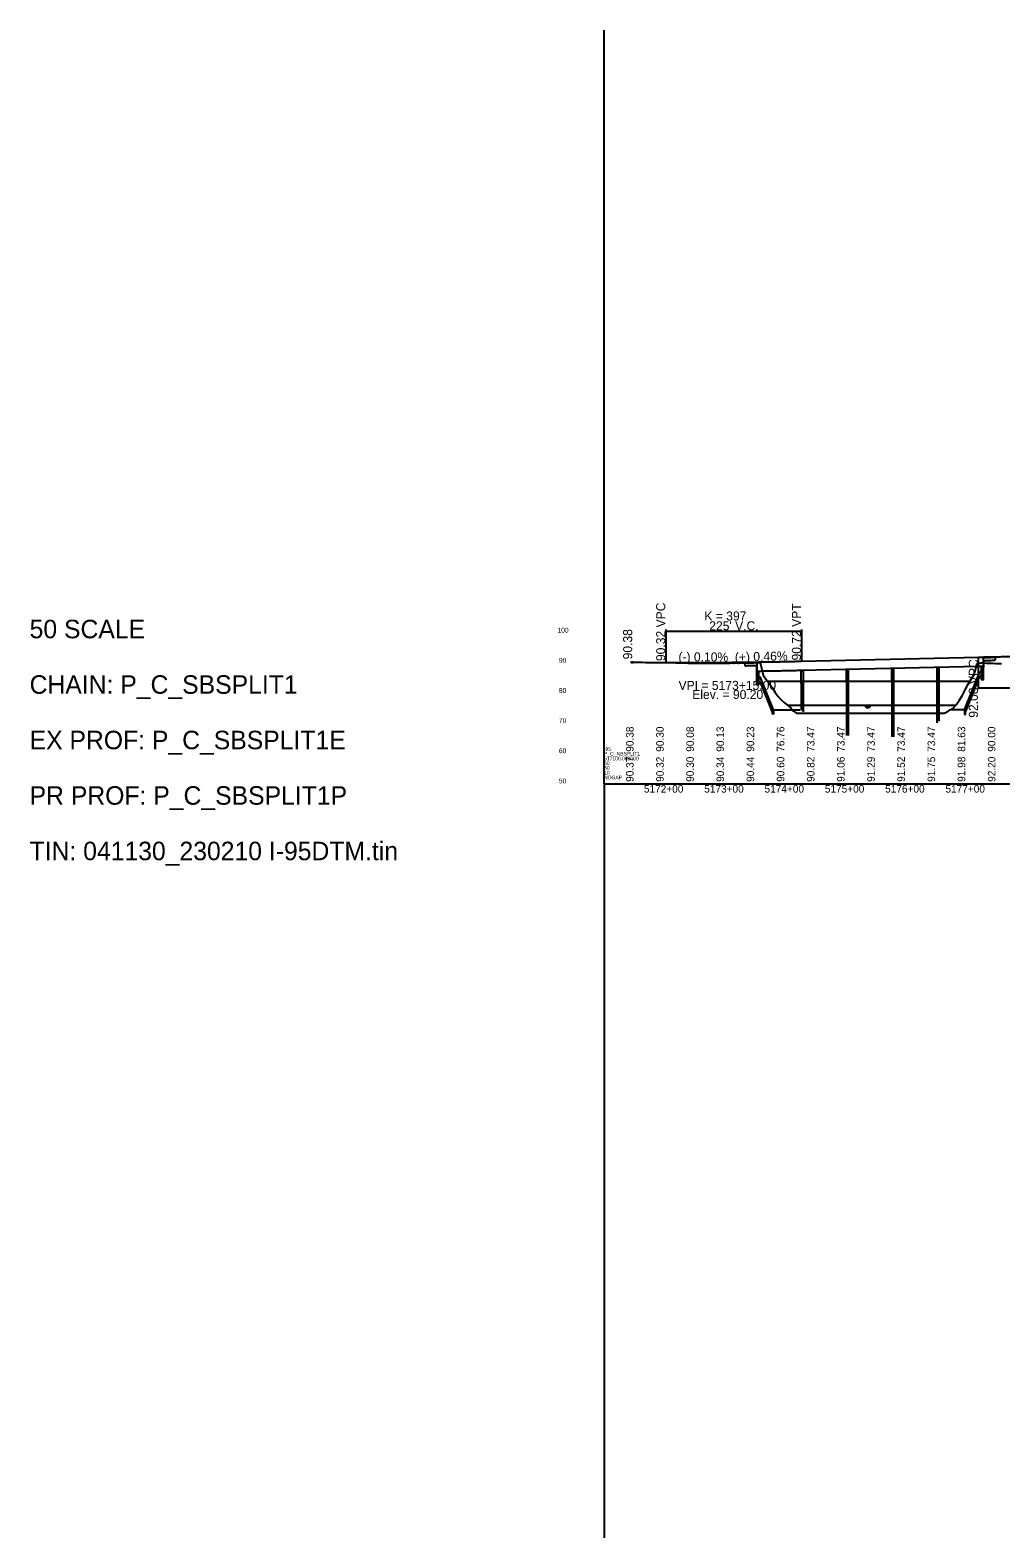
# Model space of a CAD drawing. Extents: x 2121671 to 2169879, y 557274 to 599957.
# Drawn here: x 2145717 to 2147326, y 591457 to 593957 of the extents above; entities that cross this region are included whole.
import ezdxf

# ---------------------------------------------------------------- set-up
doc = ezdxf.new("R2010")
doc.units = 0
for name, color, linetype in [('BR_CONCRETE', 7, 'Continuous'), ('BR_DETAILS', 7, 'Continuous'), ('BR_PRESTRESSED BEAM', 7, 'Continuous'), ('RD_DDB_ElevTX', 7, 'Continuous'), ('RD_DDB_GradeTX', 7, 'Continuous'), ('RD_DDB_Profile_Elev', 7, 'Continuous'), ('RD_DDB_Profile_EX', 7, 'Continuous'), ('RD_DDB_Profile_Lbl', 7, 'Continuous'), ('RD_DDB_Profile_PR', 7, 'Continuous'), ('RD_DDB_StaTX', 7, 'Continuous'), ('RD_DDB_StripGrade', 7, 'Continuous'), ('RD_DDB_VCLbl', 7, 'Continuous'), ('RD_GPK_Profile_Cell', 7, 'Continuous'), ('RD_HC_Data_Rel', 7, 'Continuous')]:
    doc.layers.add(name, color=color, linetype=linetype)

msp = doc.modelspace()

# ---------------------------------------------------------------- linework, layer by layer
at = {"layer": 'BR_CONCRETE'}
for p, q in [((2146901.8, 592908.6), (2146901.8, 592903.6)), ((2146901.8, 592908.6), (2146901.8, 592903.6)), ((2146921.1, 592903.9), (2146921.1, 592892.7)), ((2146921.1, 592903.9), (2146921.1, 592892.7)), ((2146921.8, 592909.7), (2146921.8, 592892.7)), ((2146921.8, 592909.7), (2146921.8, 592892.7)), ((2146995.7, 592911.1), (2147289.1, 592917.9)), ((2146995.7, 592911.1), (2147289.1, 592917.9)), ((2147289.1, 592917.9), (2147296.8, 592918)), ((2147289.1, 592917.9), (2147296.8, 592918)), ((2147296.8, 592918), (2147296.8, 592901)), ((2147296.8, 592918), (2147296.8, 592901)), ((2147297.5, 592912.2), (2147297.5, 592901)), ((2147297.5, 592912.2), (2147297.5, 592901)), ((2147316.8, 592917.6), (2147316.8, 592912.6)), ((2147316.8, 592917.6), (2147316.8, 592912.6)), ((2147070.3, 592875.8), (2147070.3, 592787.8)), ((2147070.3, 592875.8), (2147070.3, 592787.8)), ((2147073.3, 592875.8), (2147073.3, 592787.7)), ((2147073.3, 592875.8), (2147073.3, 592787.7)), ((2147145.3, 592877.6), (2147145.3, 592785.6)), ((2147145.3, 592877.6), (2147145.3, 592785.6)), ((2147148.3, 592877.6), (2147148.3, 592785.6)), ((2147148.3, 592877.6), (2147148.3, 592785.6)), ((2147220.3, 592879.3), (2147220.3, 592808.9)), ((2147220.3, 592879.3), (2147220.3, 592808.9)), ((2147223.3, 592879.3), (2147223.3, 592811.7)), ((2147223.3, 592879.3), (2147223.3, 592811.7)), ((2146995.3, 592874.1), (2146995.3, 592829.3)), ((2146995.3, 592874.1), (2146995.3, 592829.3)), ((2146998.3, 592874.1), (2146998.3, 592827.2)), ((2146998.3, 592874.1), (2146998.3, 592827.2))]:
    msp.add_line(p, q, dxfattribs=at)
for points in [[(2147293.5, 592881), (2147297.5, 592881), (2147297.5, 592901), (2147293.5, 592901)], [(2147293.5, 592881), (2147297.5, 592881), (2147297.5, 592901), (2147293.5, 592901)], [(2146921.1, 592872.7), (2146925.1, 592872.7), (2146925.1, 592892.7), (2146921.1, 592892.7)], [(2146921.1, 592872.7), (2146925.1, 592872.7), (2146925.1, 592892.7), (2146921.1, 592892.7)], [(2146994.8, 592874.1), (2146998.8, 592874.1), (2146998.8, 592894.1), (2146994.8, 592894.1)], [(2146994.8, 592874.1), (2146998.8, 592874.1), (2146998.8, 592894.1), (2146994.8, 592894.1)], [(2147069.8, 592875.8), (2147073.8, 592875.8), (2147073.8, 592895.8), (2147069.8, 592895.8)], [(2147069.8, 592875.8), (2147073.8, 592875.8), (2147073.8, 592895.8), (2147069.8, 592895.8)], [(2147144.8, 592877.6), (2147148.8, 592877.6), (2147148.8, 592897.6), (2147144.8, 592897.6)], [(2147144.8, 592877.6), (2147148.8, 592877.6), (2147148.8, 592897.6), (2147144.8, 592897.6)], [(2147219.8, 592879.3), (2147223.8, 592879.3), (2147223.8, 592899.3), (2147219.8, 592899.3)], [(2147219.8, 592879.3), (2147223.8, 592879.3), (2147223.8, 592899.3), (2147219.8, 592899.3)]]:
    msp.add_lwpolyline(points, close=True, dxfattribs=at)
for points in [[(2146901.8, 592908.6), (2146905.6, 592908.7), (2146910.1, 592908.7), (2146914.6, 592908.8), (2146919.1, 592908.8), (2146921.8, 592908.9)], [(2146901.8, 592908.6), (2146905.6, 592908.7), (2146910.1, 592908.7), (2146914.6, 592908.8), (2146919.1, 592908.8), (2146921.8, 592908.9)], [(2146901.8, 592903.6), (2146905.6, 592903.7), (2146910.1, 592903.7), (2146914.6, 592903.8), (2146919.1, 592903.8), (2146921.8, 592903.9)], [(2146901.8, 592903.6), (2146905.6, 592903.7), (2146910.1, 592903.7), (2146914.6, 592903.8), (2146919.1, 592903.8), (2146921.8, 592903.9)], [(2146921.8, 592909.7), (2146923.7, 592909.7), (2146928.2, 592909.8), (2146932.7, 592909.9), (2146937.2, 592909.9), (2146941.7, 592910), (2146946.2, 592910.1), (2146950.7, 592910.2), (2146955.2, 592910.2), (2146959.7, 592910.3), (2146964.2, 592910.4), (2146968.7, 592910.5), (2146973.2, 592910.6), (2146977.7, 592910.7), (2146982.2, 592910.8), (2146986.7, 592910.9), (2146991.2, 592911), (2146995.7, 592911.1)], [(2146921.8, 592909.7), (2146923.7, 592909.7), (2146928.2, 592909.8), (2146932.7, 592909.9), (2146937.2, 592909.9), (2146941.7, 592910), (2146946.2, 592910.1), (2146950.7, 592910.2), (2146955.2, 592910.2), (2146959.7, 592910.3), (2146964.2, 592910.4), (2146968.7, 592910.5), (2146973.2, 592910.6), (2146977.7, 592910.7), (2146982.2, 592910.8), (2146986.7, 592910.9), (2146991.2, 592911), (2146995.7, 592911.1)], [(2147296.8, 592917.2), (2147298.1, 592917.2), (2147307.1, 592917.4), (2147316.1, 592917.6), (2147316.8, 592917.6)], [(2147296.8, 592917.2), (2147298.1, 592917.2), (2147307.1, 592917.4), (2147316.1, 592917.6), (2147316.8, 592917.6)], [(2147296.8, 592912.2), (2147298.1, 592912.2), (2147307.1, 592912.4), (2147316.1, 592912.6), (2147316.8, 592912.6)], [(2147296.8, 592912.2), (2147298.1, 592912.2), (2147307.1, 592912.4), (2147316.1, 592912.6), (2147316.8, 592912.6)]]:
    msp.add_spline(points, degree=3, dxfattribs=at)
at = {"layer": 'BR_DETAILS'}
for p, q in [((2146925.1, 592885.2), (2146927.1, 592885.2)), ((2146925.1, 592885.2), (2146927.1, 592885.2)), ((2146925.1, 592877.7), (2146927.1, 592877.7)), ((2146925.1, 592877.7), (2146927.1, 592877.7)), ((2146949, 592830.5), (2146927.1, 592885.2)), ((2146949, 592830.5), (2146927.1, 592885.2)), ((2146947.5, 592826.7), (2146927.1, 592877.7)), ((2146947.5, 592826.7), (2146927.1, 592877.7)), ((2147266.2, 592830.4), (2147291.5, 592893.5)), ((2147266.2, 592830.4), (2147291.5, 592893.5)), ((2147267.7, 592826.7), (2147291.5, 592886)), ((2147267.7, 592826.7), (2147291.5, 592886)), ((2147293.5, 592893.5), (2147291.5, 592893.5)), ((2147293.5, 592893.5), (2147291.5, 592893.5)), ((2147293.5, 592886), (2147291.5, 592886)), ((2147293.5, 592886), (2147291.5, 592886)), ((2146947.5, 592823), (2146947.5, 592826.7)), ((2146947.5, 592823), (2146947.5, 592826.7)), ((2146949, 592830.5), (2146993, 592830.5)), ((2146949, 592830.5), (2146949, 592823)), ((2146949, 592830.5), (2146993, 592830.5)), ((2146949, 592830.5), (2146949, 592823)), ((2147266.2, 592830.4), (2147244.7, 592830.4)), ((2147266.2, 592830.4), (2147244.7, 592830.4)), ((2147266.2, 592830.4), (2147266.2, 592822.9)), ((2147266.2, 592830.4), (2147266.2, 592822.9)), ((2147267.7, 592822.9), (2147267.7, 592826.7)), ((2147267.7, 592822.9), (2147267.7, 592826.7)), ((2146949, 592823), (2146947.5, 592823)), ((2146949, 592823), (2146947.5, 592823)), ((2147266.2, 592822.9), (2147267.7, 592822.9)), ((2147266.2, 592822.9), (2147267.7, 592822.9))]:
    msp.add_line(p, q, dxfattribs=at)
at = {"layer": 'BR_PRESTRESSED BEAM'}
for p, q in [((2146995.7, 592896.1), (2147289.1, 592902.9)), ((2146995.7, 592896.1), (2147289.1, 592902.9)), ((2147289.1, 592902.9), (2147296.8, 592903)), ((2147289.1, 592902.9), (2147296.8, 592903))]:
    msp.add_line(p, q, dxfattribs=at)
msp.add_spline([(2146921.8, 592894.7), (2146923.7, 592894.7), (2146928.2, 592894.8), (2146932.7, 592894.9), (2146937.2, 592894.9), (2146941.7, 592895), (2146946.2, 592895.1), (2146950.7, 592895.2), (2146955.2, 592895.2), (2146959.7, 592895.3), (2146964.2, 592895.4), (2146968.7, 592895.5), (2146973.2, 592895.6), (2146977.7, 592895.7), (2146982.2, 592895.8), (2146986.7, 592895.9), (2146991.2, 592896), (2146995.7, 592896.1)], degree=3, dxfattribs=at)
msp.add_spline([(2146921.8, 592894.7), (2146923.7, 592894.7), (2146928.2, 592894.8), (2146932.7, 592894.9), (2146937.2, 592894.9), (2146941.7, 592895), (2146946.2, 592895.1), (2146950.7, 592895.2), (2146955.2, 592895.2), (2146959.7, 592895.3), (2146964.2, 592895.4), (2146968.7, 592895.5), (2146973.2, 592895.6), (2146977.7, 592895.7), (2146982.2, 592895.8), (2146986.7, 592895.9), (2146991.2, 592896), (2146995.7, 592896.1)], degree=3, dxfattribs=at)
at = {"layer": 'RD_DDB_GradeTX'}
for p, q in [((2146821.2, 592908.8), (2146882.2, 592908.5)), ((2146945.2, 592909.9), (2146884.2, 592908.5))]:
    msp.add_line(p, q, dxfattribs=at)
for centre in [(2146715.2, 592909.3), (2146883.2, 592908.5)]:
    msp.add_circle(centre, 1, dxfattribs=at)
at = {"layer": 'RD_DDB_Profile_Elev'}
for p, q in [((2146939.2, 592878.1), (2147275.3, 592878.1)), ((2146972.4, 592838.1), (2147251.5, 592838.1)), ((2147100.5, 592836.8), (2147110.5, 592836.8)), ((2147101.7, 592835.6), (2147109.2, 592835.6)), ((2147103, 592834.3), (2147108, 592834.3))]:
    msp.add_line(p, q, dxfattribs=at)
at = {"layer": 'RD_DDB_Profile_EX'}
for points in [[(2146712.2, 592909.4), (2146717.2, 592909.4), (2146722.2, 592909.3), (2146727.2, 592909.3), (2146732.2, 592909.3), (2146737.2, 592909.2), (2146742.2, 592909.2), (2146747.2, 592909.2), (2146752.2, 592909.1), (2146757.2, 592909.1), (2146762.2, 592909), (2146767.2, 592909), (2146772.2, 592908.9), (2146777.2, 592908.8), (2146782.2, 592908.7), (2146787.2, 592908.6), (2146792.2, 592908.4), (2146797.2, 592908.3), (2146802.2, 592908.2), (2146807.2, 592908.1), (2146812.2, 592908), (2146817.2, 592907.9), (2146822.2, 592907.8), (2146827.2, 592907.7), (2146832.2, 592907.8), (2146837.2, 592907.8), (2146842.2, 592907.9), (2146847.2, 592907.9), (2146852.2, 592908), (2146857.2, 592908), (2146862.2, 592908.1), (2146867.2, 592908.1), (2146872.2, 592908.1), (2146877.2, 592908.1), (2146882.2, 592908.2), (2146887.2, 592908.2), (2146892.2, 592908.2), (2146897.2, 592908.3), (2146902.2, 592908.4), (2146907.2, 592908.4), (2146912.2, 592908.5), (2146917.2, 592908.6), (2146922.2, 592908.7), (2146927.2, 592908.8), (2146932.2, 592887.9), (2146937.2, 592880.5), (2146942.2, 592874.5), (2146947.2, 592867.6), (2146952.2, 592859), (2146957.2, 592852.7), (2146962.2, 592847), (2146967.2, 592842), (2146972.2, 592838.2), (2146977.2, 592834.1), (2146982.2, 592828), (2146987.2, 592824.8), (2146992.2, 592824.8), (2146997.2, 592824.8), (2147002.2, 592824.8), (2147007.2, 592824.8), (2147012.2, 592824.8), (2147017.2, 592824.8), (2147022.2, 592824.8), (2147027.2, 592824.8), (2147032.2, 592824.8), (2147037.2, 592824.8), (2147042.2, 592824.8), (2147047.2, 592824.8), (2147052.2, 592824.8), (2147057.2, 592824.8), (2147062.2, 592824.8), (2147067.2, 592824.8), (2147072.2, 592824.8), (2147077.2, 592824.8), (2147082.2, 592824.8), (2147087.2, 592824.8), (2147092.2, 592824.8), (2147097.2, 592824.8), (2147102.2, 592824.8), (2147107.2, 592824.8), (2147112.2, 592824.8), (2147117.2, 592824.8), (2147122.2, 592824.8), (2147127.2, 592824.8), (2147132.2, 592824.8), (2147137.2, 592824.8), (2147142.2, 592824.8), (2147147.2, 592824.8), (2147152.2, 592824.8), (2147157.2, 592824.8), (2147162.2, 592824.8), (2147167.2, 592824.8), (2147172.2, 592824.8), (2147177.2, 592824.8), (2147182.2, 592824.8), (2147187.2, 592824.8), (2147192.2, 592824.8), (2147197.2, 592824.8), (2147202.2, 592824.8), (2147207.2, 592824.8), (2147212.2, 592824.8)], [(2147212.2, 592824.8), (2147217.2, 592824.8), (2147222.2, 592824.8), (2147227.2, 592824.8), (2147232.2, 592824.8), (2147237.2, 592827.4), (2147242.2, 592830.3), (2147247.2, 592833.3), (2147252.2, 592838.8), (2147257.2, 592845.8), (2147262.2, 592853.9), (2147267.2, 592863.8), (2147272.2, 592873.2), (2147277.2, 592881.3), (2147282.2, 592889.1), (2147287.2, 592906.8), (2147292.2, 592908.3), (2147297.2, 592908.2), (2147302.2, 592908), (2147307.2, 592907.8), (2147312.2, 592907.7), (2147317.2, 592907.5), (2147322.2, 592907.3), (2147327.2, 592907.2)]]:
    msp.add_lwpolyline(points, dxfattribs=at)
at = {"layer": 'RD_DDB_Profile_PR'}
for p, q in [((2146715.2, 592909.3), (2146770.7, 592909.1)), ((2146995.7, 592911.1), (2147289.1, 592917.9))]:
    msp.add_line(p, q, dxfattribs=at)
for points in [[(2146770.7, 592909.1), (2146775.2, 592909), (2146779.7, 592909), (2146784.2, 592909), (2146788.7, 592909), (2146793.2, 592909), (2146797.7, 592909), (2146802.2, 592909), (2146806.7, 592909), (2146811.2, 592908.9), (2146815.7, 592908.9), (2146820.2, 592909), (2146824.7, 592909), (2146829.2, 592909), (2146833.7, 592909), (2146838.2, 592909), (2146842.7, 592909), (2146847.2, 592909), (2146851.7, 592909), (2146856.2, 592909.1), (2146860.7, 592909.1), (2146865.2, 592909.1), (2146869.7, 592909.2), (2146874.2, 592909.2), (2146878.7, 592909.2), (2146883.2, 592909.3), (2146887.7, 592909.3), (2146892.2, 592909.4), (2146896.7, 592909.4), (2146901.2, 592909.4), (2146905.7, 592909.5), (2146910.2, 592909.6), (2146914.7, 592909.6), (2146919.2, 592909.7), (2146923.7, 592909.7), (2146928.2, 592909.8), (2146932.7, 592909.9), (2146937.2, 592909.9), (2146941.7, 592910), (2146946.2, 592910.1), (2146950.7, 592910.2), (2146955.2, 592910.2), (2146959.7, 592910.3), (2146964.2, 592910.4), (2146968.7, 592910.5), (2146973.2, 592910.6), (2146977.7, 592910.7), (2146982.2, 592910.8), (2146986.7, 592910.9), (2146991.2, 592911), (2146995.7, 592911.1)], [(2147289.1, 592917.9), (2147298.1, 592918.1), (2147307.1, 592918.3), (2147316.1, 592918.4), (2147325.1, 592918.6), (2147334.1, 592918.8), (2147343.1, 592918.9), (2147352.1, 592919.1), (2147361.1, 592919.2), (2147370.1, 592919.4), (2147379.1, 592919.5), (2147388.1, 592919.6), (2147397.1, 592919.7), (2147406.1, 592919.8), (2147415.1, 592919.9), (2147424.1, 592920), (2147433.1, 592920), (2147442.1, 592920.1), (2147451.1, 592920.2), (2147460.1, 592920.2), (2147469.1, 592920.2), (2147478.1, 592920.3), (2147487.1, 592920.3), (2147496.1, 592920.3), (2147505.1, 592920.3), (2147514.1, 592920.3), (2147523.1, 592920.2), (2147532.1, 592920.2), (2147541.1, 592920.2), (2147550.1, 592920.1), (2147559.1, 592920.1), (2147568.1, 592920), (2147577.1, 592919.9), (2147586.1, 592919.8), (2147595.1, 592919.7), (2147604.1, 592919.6), (2147613.1, 592919.5), (2147622.1, 592919.4), (2147631.1, 592919.3), (2147640.1, 592919.1), (2147649.1, 592919), (2147658.1, 592918.8), (2147667.1, 592918.7), (2147676.1, 592918.5), (2147685.1, 592918.3), (2147694.1, 592918.1), (2147703.1, 592917.9), (2147712.1, 592917.7), (2147721.1, 592917.5), (2147730.1, 592917.3), (2147739.1, 592917)]]:
    msp.add_spline(points, degree=3, dxfattribs=at)
at = {"layer": 'RD_DDB_VCLbl'}
for p, q in [((2146770.7, 592963.6), (2146770.7, 592909.1)), ((2146770.7, 592961.1), (2146995.7, 592961.1)), ((2146995.7, 592963.6), (2146995.7, 592911.1)), ((2147289.1, 592864.5), (2147289.1, 592917.9)), ((2147289.1, 592867), (2147739.1, 592867))]:
    msp.add_line(p, q, dxfattribs=at)
at = {"layer": 'RD_GPK_Profile_Cell'}
for q in [(2146668.2, 593957.5), (2146668.2, 593957.5), (2151268.2, 592707.5), (2146668.2, 591457.5), (2151268.2, 592707.5), (2146668.2, 591457.5)]:
    msp.add_line((2146668.2, 592707.5), q, dxfattribs=at)

# ---------------------------------------------------------------- texts
at = {"layer": 'RD_DDB_ElevTX'}
for s, p in [('100', (2146591, 592958.5)), ('90', (2146593.4, 592908.5)), ('80', (2146593.4, 592858.5)), ('70', (2146593.4, 592808.5)), ('60', (2146593.4, 592758.5)), ('50', (2146593.4, 592708.5))]:
    msp.add_text(s, height=8, dxfattribs=at).set_placement(p)
at = {"layer": 'RD_DDB_GradeTX'}
for s, rotation, p in [('(-) 0.10%', 359.7004, (2146791.6, 592910.9)), ('(+) 0.46%', 1.3258, (2146885.3, 592910.5))]:
    msp.add_text(s, height=15, rotation=rotation, dxfattribs=at).set_placement(p)
at = {"layer": 'RD_DDB_Profile_Lbl'}
msp.add_text('90.38', height=15, rotation=90, dxfattribs=at).set_placement((2146714.9, 592914.1))
for s, p in [('VPI = 5173+15.00', (2146791.8, 592863.5)), ('Elev. = 90.20', (2146814.5, 592848.5))]:
    msp.add_text(s, height=15, dxfattribs=at).set_placement(p)
at = {"layer": 'RD_DDB_StaTX'}
for s, p in [('5172+00', (2146734.3, 592693.2)), ('5173+00', (2146834.3, 592693.2)), ('5174+00', (2146934.3, 592693.2)), ('5175+00', (2147034.3, 592693.2)), ('5176+00', (2147134.3, 592693.2)), ('5177+00', (2147234.3, 592693.2))]:
    msp.add_text(s, height=12.5, dxfattribs=at).set_placement(p)
at = {"layer": 'RD_DDB_StripGrade'}
for s, height, p in [('90.32 VPC', 15, (2146769.7, 592911.3)), ('90.72 VPT', 15, (2146994.7, 592912.3)), ('92.08 VPC', 15, (2147288.1, 592817.3)), ('90.38', 12.5, (2146717.2, 592760.9)), ('90.30', 12.5, (2146767.2, 592760.9)), ('90.08', 12.5, (2146817.2, 592760.9)), ('90.13', 12.5, (2146867.2, 592760.9)), ('90.23', 12.5, (2146917.2, 592760.9)), ('76.76', 12.5, (2146967.2, 592760.9)), ('73.47', 12.5, (2147017.2, 592760.9)), ('73.47', 12.5, (2147067.2, 592760.9)), ('73.47', 12.5, (2147117.2, 592760.9)), ('73.47', 12.5, (2147167.2, 592760.9)), ('73.47', 12.5, (2147217.2, 592760.9)), ('81.63', 12.5, (2147267.2, 592760.9)), ('90.00', 12.5, (2147317.2, 592760.9)), ('90.37', 12.5, (2146717.2, 592711)), ('90.32', 12.5, (2146767.2, 592711)), ('90.30', 12.5, (2146817.2, 592711)), ('90.34', 12.5, (2146867.2, 592711)), ('90.44', 12.5, (2146917.2, 592711)), ('90.60', 12.5, (2146967.2, 592711)), ('90.82', 12.5, (2147017.2, 592711)), ('91.06', 12.5, (2147067.2, 592711)), ('91.29', 12.5, (2147117.2, 592711)), ('91.52', 12.5, (2147167.2, 592711)), ('91.75', 12.5, (2147217.2, 592711)), ('91.98', 12.5, (2147267.2, 592711)), ('92.20', 12.5, (2147317.2, 592711))]:
    msp.add_text(s, height=height, rotation=90, dxfattribs=at).set_placement(p)
at = {"layer": 'RD_DDB_VCLbl'}
for s, p in [('K = 397', (2146834.6, 592978.6)), ("225' V.C.", (2146842.7, 592962.3))]:
    msp.add_text(s, height=15, dxfattribs=at).set_placement(p)
at = {"layer": 'RD_GPK_Profile_Cell'}
for s, height, p in [('517100.000000', 6, (2146668.2, 592746.8)), ('P_C_NBSPLIT1', 6, (2146668.2, 592754.7)), ('I95', 6, (2146668.2, 592762.5)), ('50', 6, (2146668.2, 592738.9)), ('50', 6, (2146668.2, 592731.1)), ('10', 6, (2146668.2, 592723.2)), ('I95', 0.208, (2146668.2, 592711.8)), ('P_C_SBSPLIT1', 0.208, (2146668.2, 592711.2)), ('517100.000000', 0.208, (2146668.2, 592710.6)), ('50', 0.208, (2146668.2, 592710)), ('50', 0.208, (2146668.2, 592709.3)), ('10', 0.208, (2146668.2, 592708.7)), ('NOGAP', 0.208, (2146668.2, 592708.1)), ('NOGAP', 6, (2146668.2, 592715.3))]:
    msp.add_text(s, height=height, dxfattribs=at).set_placement(p)
at = {"layer": 'RD_HC_Data_Rel'}
for s, height, p in [('50 SCALE', 30.67, (2145715.7, 592949.1)), ('CHAIN: P_C_SBSPLIT1', 30.668, (2145715.7, 592857.1)), ('EX PROF: P_C_SBSPLIT1E', 30.668, (2145715.7, 592765.1)), ('PR PROF: P_C_SBSPLIT1P', 30.668, (2145715.7, 592673.1)), ('TIN: 041130_230210 I-95DTM.tin', 30.668, (2145715.7, 592581.1))]:
    msp.add_text(s, height=height, rotation=360, dxfattribs=at).set_placement(p)

doc.saveas('drawing.dxf')
